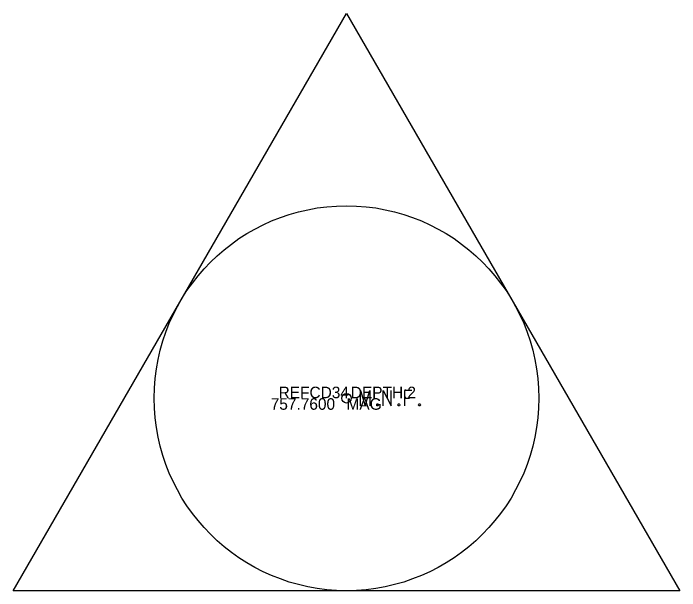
# Model space of a CAD drawing. Extents: x 1775010 to 1779939, y 521137 to 529228.
# Drawn here: x 1777748.711 to 1777752.175, y 525555.591 to 525558.591 of the extents above; entities that cross this region are included whole.
import ezdxf

# ---------------------------------------------------------------- set-up
doc = ezdxf.new("R2010")
doc.units = 0
for name, color, linetype in [('SV_Control_Point', 7, 'Continuous'), ('SV_X_Control_Cells_Found', 7, 'Continuous'), ('SV_X_Text_Comment', 7, 'Continuous'), ('SV_X_Text_Description', 7, 'Continuous'), ('SV_X_Text_Elevation', 7, 'Continuous'), ('SV_X_Text_Name', 7, 'Continuous')]:
    doc.layers.add(name, color=color, linetype=linetype)

msp = doc.modelspace()

# ---------------------------------------------------------------- linework, layer by layer
at = {"layer": 'SV_Control_Point'}
for p, q in [((1777748.7109, 525555.5908), (1777750.443, 525558.5908)), ((1777750.443, 525558.5908), (1777752.1751, 525555.5908)), ((1777750.443, 525556.5908), (1777750.443, 525556.5908)), ((1777752.1751, 525555.5908), (1777748.7109, 525555.5908))]:
    msp.add_line(p, q, dxfattribs=at)
msp.add_circle((1777750.443, 525556.5908), 1, dxfattribs=at)
at = {"layer": 'SV_X_Control_Cells_Found'}
for points in [[(1777750.515, 525556.5504), (1777750.515, 525556.6304), (1777750.5404, 525556.5504), (1777750.5646, 525556.6304), (1777750.5646, 525556.5504)], [(1777750.6335, 525556.5504), (1777750.6335, 525556.6304), (1777750.6749, 525556.5504), (1777750.6749, 525556.6304)], [(1777750.7823, 525556.6304), (1777750.7443, 525556.6304), (1777750.7443, 525556.5504)], [(1777750.6032, 525556.5611), (1777750.606, 525556.5611), (1777750.6076, 525556.5598), (1777750.6093, 525556.5573), (1777750.6093, 525556.5542), (1777750.6076, 525556.5516), (1777750.606, 525556.5504), (1777750.6032, 525556.5504), (1777750.6015, 525556.5516), (1777750.5999, 525556.5542), (1777750.5999, 525556.5573), (1777750.6015, 525556.5598), (1777750.6032, 525556.5611)], [(1777750.714, 525556.5611), (1777750.7167, 525556.5611), (1777750.7184, 525556.5598), (1777750.72, 525556.5573), (1777750.72, 525556.5542), (1777750.7184, 525556.5516), (1777750.7167, 525556.5504), (1777750.714, 525556.5504), (1777750.7123, 525556.5516), (1777750.7107, 525556.5542), (1777750.7107, 525556.5573), (1777750.7123, 525556.5598), (1777750.714, 525556.5611)], [(1777750.7443, 525556.5913), (1777750.7713, 525556.5913)], [(1777750.8215, 525556.5611), (1777750.8242, 525556.5611), (1777750.8259, 525556.5598), (1777750.8275, 525556.5573), (1777750.8275, 525556.5542), (1777750.8259, 525556.5516), (1777750.8242, 525556.5504), (1777750.8215, 525556.5504), (1777750.8198, 525556.5516), (1777750.8181, 525556.5542), (1777750.8181, 525556.5573), (1777750.8198, 525556.5598), (1777750.8215, 525556.5611)]]:
    msp.add_lwpolyline(points, dxfattribs=at)
msp.add_circle((1777750.443, 525556.5908), 0.0249, dxfattribs=at)

# ---------------------------------------------------------------- texts
at = {"layer": 'SV_X_Text_Comment'}
msp.add_text('MAG', height=0.06, dxfattribs=at).set_placement((1777750.443, 525556.5308))
at = {"layer": 'SV_X_Text_Description'}
msp.add_text(' DEPTH:2', height=0.06, dxfattribs=at).set_placement((1777750.443, 525556.5908))
at = {"layer": 'SV_X_Text_Elevation'}
msp.add_text('757.7600', height=0.06, dxfattribs=at).set_placement((1777750.049, 525556.5308))
at = {"layer": 'SV_X_Text_Name'}
msp.add_text('REFCD34', height=0.06, dxfattribs=at).set_placement((1777750.0901, 525556.5908))

doc.saveas('drawing.dxf')
